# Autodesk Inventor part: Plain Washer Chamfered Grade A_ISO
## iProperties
Created: 2011-02
Part Number: Plain Washer Chamfered Grade A_ISO
Document SubType Name: Modeling
Designer: eric
Density: 1 g/cm^3
Author: eric
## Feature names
1. Base1
